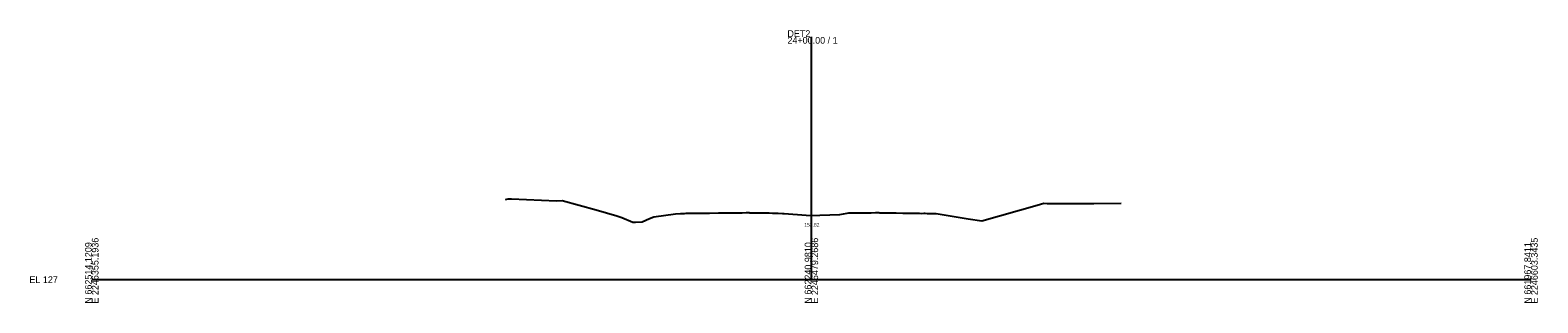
# Model space of a CAD drawing. Extents: x -26 to 603, y -10 to 9526.
# Drawn here: x -26 to 603, y 6990 to 7104 of the extents above; entities that cross this region are included whole.
import ezdxf

# ---------------------------------------------------------------- set-up
doc = ezdxf.new("R2010")
doc.units = 0
for name, color, linetype in [('Default', 7, 'Continuous'), ('Exist Cross Section Cell', 7, 'Continuous'), ('Exist XS Center Line Elevation Label', 7, 'Continuous'), ('Exist XS Ground Line', 7, 'Continuous')]:
    doc.layers.add(name, color=color, linetype=linetype)

msp = doc.modelspace()

# ---------------------------------------------------------------- linework, layer by layer
at = {"layer": 'Exist Cross Section Cell'}
for p, q in [((300, 7000), (300, 7101.21)), ((0, 7000), (300, 7000)), ((300, 7000), (600, 7000))]:
    msp.add_line(p, q, dxfattribs=at)
at = {"layer": 'Exist XS Ground Line'}
for p, q in [((172.45, 7033.44), (173.6, 7033.74)), ((173.6, 7033.74), (174.96, 7033.66)), ((174.96, 7033.66), (193.7, 7032.89)), ((193.7, 7032.89), (196.14, 7032.97)), ((196.14, 7032.97), (210.2, 7029.1)), ((210.2, 7029.1), (218.95, 7026.58)), ((234.25, 7026.16), (243.38, 7027.38)), ((243.38, 7027.38), (245.4, 7027.64)), ((245.4, 7027.64), (246.14, 7027.59)), ((246.14, 7027.59), (246.46, 7027.59)), ((246.46, 7027.59), (247.11, 7027.62)), ((247.11, 7027.62), (247.78, 7027.66)), ((247.78, 7027.66), (248.5, 7027.68)), ((248.5, 7027.68), (249.17, 7027.71)), ((249.17, 7027.71), (249.6, 7027.71)), ((249.6, 7027.71), (251.65, 7027.73)), ((251.65, 7027.73), (252.2, 7027.73)), ((252.2, 7027.73), (253.41, 7027.74)), ((253.41, 7027.74), (257.14, 7027.76)), ((257.14, 7027.76), (257.46, 7027.77)), ((257.46, 7027.77), (261.28, 7027.82)), ((261.28, 7027.82), (261.69, 7027.86)), ((261.69, 7027.86), (262.39, 7027.83)), ((262.39, 7027.83), (263.17, 7027.81)), ((263.17, 7027.81), (263.53, 7027.82)), ((263.53, 7027.82), (265.5, 7027.84)), ((265.5, 7027.84), (267.31, 7027.86)), ((267.31, 7027.86), (268.13, 7027.88)), ((268.13, 7027.88), (271.08, 7027.91)), ((271.08, 7027.91), (272.83, 7027.95)), ((272.83, 7027.95), (273.7, 7028.01)), ((273.7, 7028.01), (274.03, 7027.98)), ((274.03, 7027.98), (274.35, 7027.92)), ((274.35, 7027.92), (274.86, 7027.91)), ((274.86, 7027.91), (277.59, 7027.88)), ((277.59, 7027.88), (278.64, 7027.87)), ((278.64, 7027.87), (279.11, 7027.87)), ((279.11, 7027.87), (282.41, 7027.8)), ((282.41, 7027.8), (283.71, 7027.77)), ((283.71, 7027.77), (284.64, 7027.78)), ((284.64, 7027.78), (285.22, 7027.78)), ((285.22, 7027.78), (285.54, 7027.71)), ((285.54, 7027.71), (286.19, 7027.72)), ((286.19, 7027.72), (287.89, 7027.63)), ((287.89, 7027.63), (288.66, 7027.56)), ((288.66, 7027.56), (297.83, 7026.93)), ((303.55, 7026.93), (311.78, 7027.19)), ((311.78, 7027.19), (314.9, 7027.68)), ((314.9, 7027.68), (315.62, 7027.79)), ((315.62, 7027.79), (316.3, 7027.79)), ((316.3, 7027.79), (317.55, 7027.8)), ((317.55, 7027.8), (320.17, 7027.83)), ((320.17, 7027.83), (323.04, 7027.88)), ((323.04, 7027.88), (324.91, 7027.91)), ((324.91, 7027.91), (326.7, 7027.95)), ((326.7, 7027.95), (327.03, 7027.96)), ((327.03, 7027.96), (328.04, 7027.94)), ((328.04, 7027.94), (328.54, 7027.92)), ((328.54, 7027.92), (330.69, 7027.89)), ((330.69, 7027.89), (334.03, 7027.85)), ((334.03, 7027.85), (335.28, 7027.83)), ((335.28, 7027.83), (338.09, 7027.78)), ((338.09, 7027.78), (339.2, 7027.75)), ((339.2, 7027.75), (339.52, 7027.78)), ((339.52, 7027.78), (342.83, 7027.72)), ((342.83, 7027.72), (345.01, 7027.67)), ((345.01, 7027.67), (345.96, 7027.64)), ((345.96, 7027.64), (346.86, 7027.67)), ((346.86, 7027.67), (347.42, 7027.66)), ((347.42, 7027.66), (348.2, 7027.63)), ((348.2, 7027.63), (350.45, 7027.58)), ((350.45, 7027.58), (351.02, 7027.54)), ((351.02, 7027.54), (352.04, 7027.52)), ((352.04, 7027.52), (365.39, 7025.37)), ((371.06, 7024.47), (394.06, 7031.06)), ((394.06, 7031.06), (396.84, 7031.82)), ((396.84, 7031.82), (398.25, 7031.81)), ((398.25, 7031.81), (417.75, 7031.74)), ((417.75, 7031.74), (429.16, 7031.82)), ((218.95, 7026.58), (221, 7025.93)), ((221, 7025.93), (225.57, 7023.96)), ((225.57, 7023.96), (226.61, 7023.98)), ((226.61, 7023.98), (229.39, 7024.11)), ((229.39, 7024.11), (232.49, 7025.44)), ((232.49, 7025.44), (234.25, 7026.16)), ((297.83, 7026.93), (299.76, 7026.81)), ((299.76, 7026.81), (303.55, 7026.93)), ((365.39, 7025.37), (371.06, 7024.47))]:
    msp.add_line(p, q, dxfattribs=at)

# ---------------------------------------------------------------- texts
at = {"layer": 'Default'}
msp.add_text('-', height=0.0001, dxfattribs=at).set_placement((0, 7000))
msp.add_text('-', height=0.0001, dxfattribs=at).set_placement((0, 7000))
msp.add_text('-', height=0.0001, dxfattribs=at).set_placement((0, 7000))
at = {"layer": 'Exist Cross Section Cell'}
for s, p in [('DET2', (290, 7101.21)), ('24+00.00 / 1', (290, 7098.41)), ('EL 127', (-26, 6998.6))]:
    msp.add_text(s, height=2.8, dxfattribs=at).set_placement(p)
for s, p in [('N 662514.1209', (0, 6990)), ('E 2246355.1936', (2.8, 6990)), ('N 662240.9810', (300, 6990)), ('E 2246479.2686', (302.8, 6990)), ('N 661967.8411', (600, 6990)), ('E 2246603.3435', (602.8, 6990))]:
    msp.add_text(s, height=2.8, rotation=90, dxfattribs=at).set_placement(p)
at = {"layer": 'Exist XS Center Line Elevation Label'}
msp.add_text('153.82', height=1.5, dxfattribs=at).set_placement((297.02, 7022.07))

doc.saveas('drawing.dxf')
